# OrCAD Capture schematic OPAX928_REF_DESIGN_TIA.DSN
size A; title: OPA928: 36V, Femotampere Input Bias, High Precision Op Amp; rev: 1.1; note: Datasheet: SBOSA77A - APR '24   EVM: SBOU282A
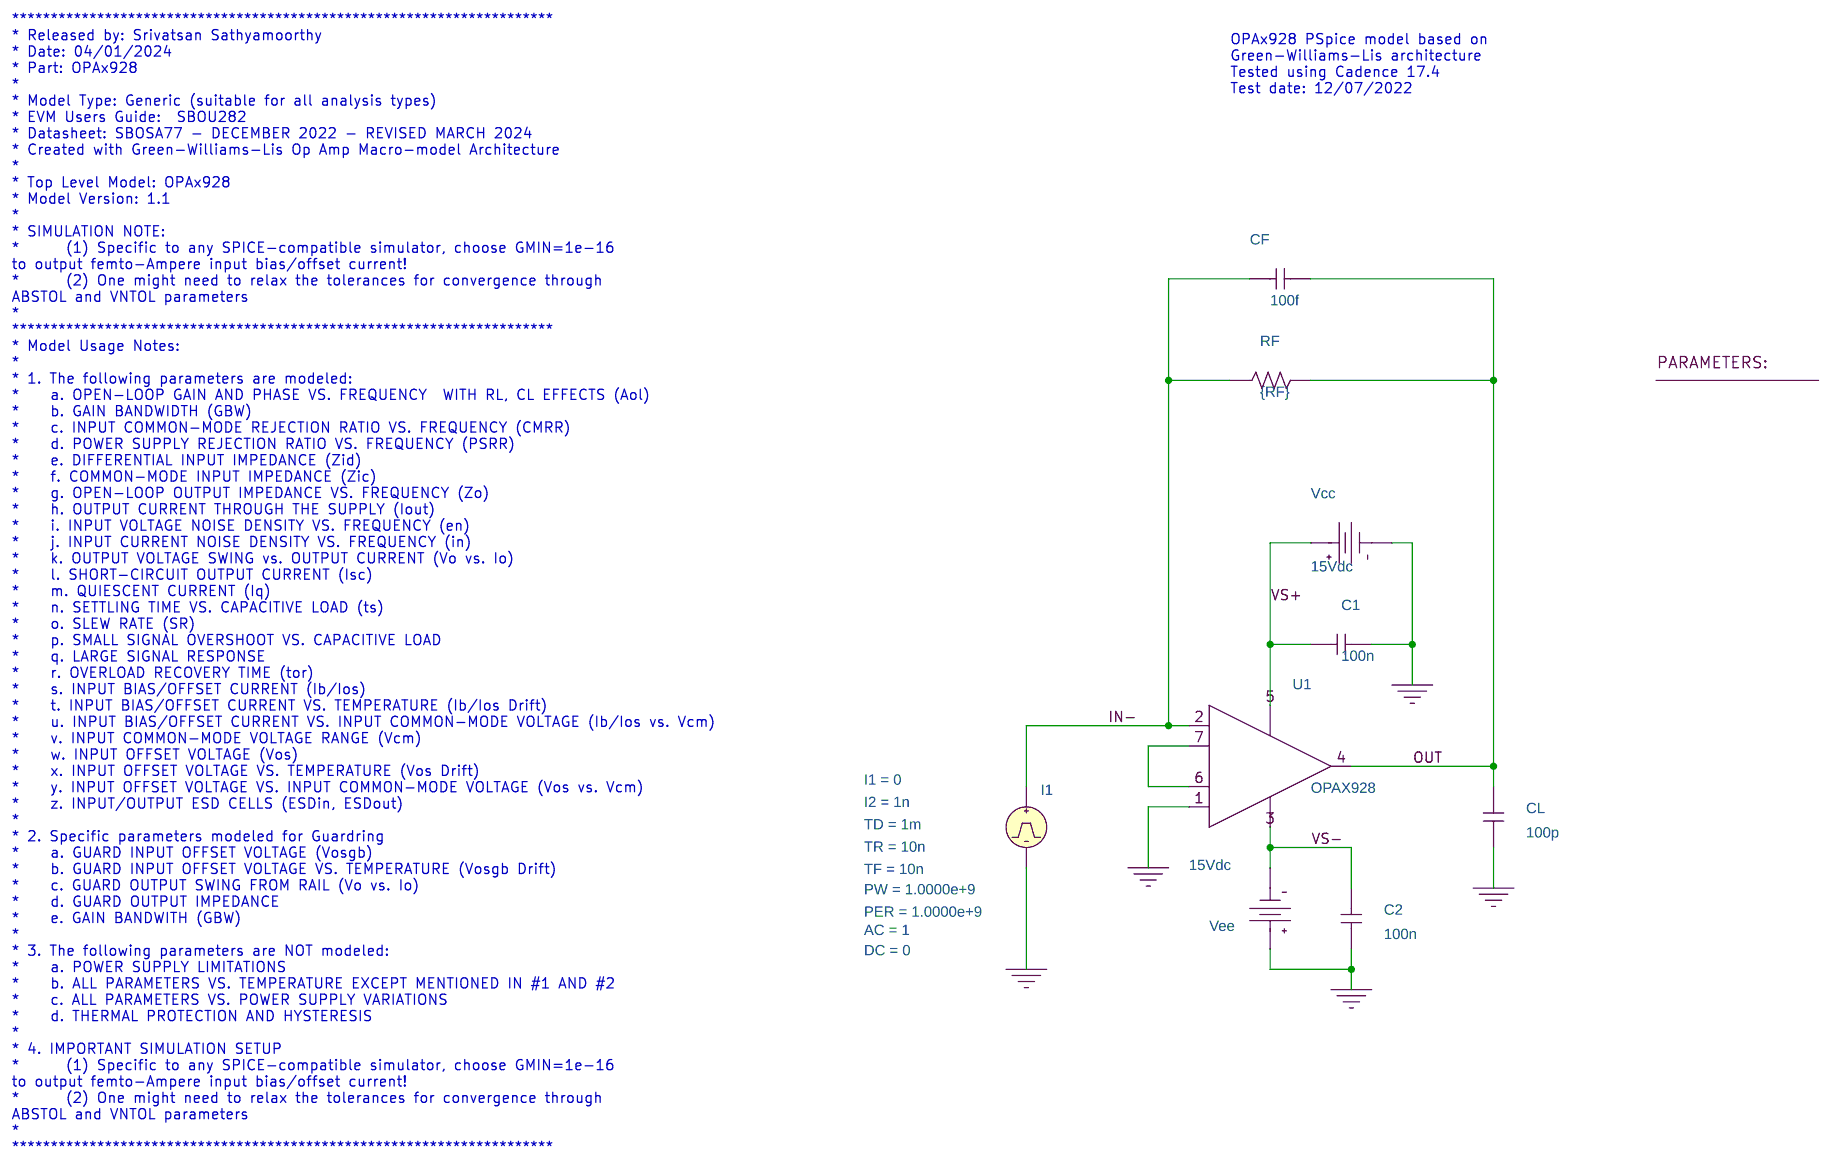
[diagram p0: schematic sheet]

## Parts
1  PARAM
C1  100n  [cap196]
C2  100n  [cap196]
CF  100f  [cap196]
CL  100p  [cap196]
I1  IPULSE
RF  {RF}  [AXRC05]
U1  OPAX928
Vcc  VDC
Vee  VDC

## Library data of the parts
1 = PARAM: RF: 10G
C1 C2 CF CL = C
I1 = IPULSE: AC: 1; AppProp: Pulse$Current$0$-1; DC: 0; I1: 0; I2: 1n; PER: 1.0000e+9; PW: 1.0000e+9; TD: 1m; TF: 10n; TR: 10n
RF = R
U1 = OPAX928
Vcc Vee = VDC: DC: 15Vdc

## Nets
0: C1.2 C2.1 CL.1 I1.2(-) U1.1(+) Vcc.1(-) Vee.0(+)
IN-: CF.2 I1.1(+) RF.1 U1.2(-)
OUT: CF.1 CL.2 RF.2 U1.4(OUT)
VS+: C1.1 U1.5(V+) Vcc.0(+)
VS-: C2.2 U1.3(V-) Vee.1(-)
N00104: U1.6(GRD1) U1.7(GRD2)

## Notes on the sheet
- **********************************************************************
  * Released by: Srivatsan Sathyamoorthy
  * Date: 04/01/2024
  * Part: OPAx928
  *
  * Model Type: Generic (suitable for all analysis types)
  * EVM Users Guide:  SBOU282
  * Datasheet: SBOSA77 - DECEMBER 2022 - REVISED MARCH 2024
  * Created with Green-Williams-Lis Op Amp Macro-model Architecture
  *
  * Top Level Model: OPAx928
  * Model Version: 1.1
  *
  * SIMULATION NOTE:
  *      (1) Specific to any SPICE-compatible simulator, choose GMIN=1e-16
  to output femto-Ampere input bias/offset current!
  *      (2) One might need to relax the tolerances for convergence through
  ABSTOL and VNTOL parameters
  *
  **********************************************************************
  * Model Usage Notes:
  *
  * 1. The following parameters are modeled:
  *    a. OPEN-LOOP GAIN AND PHASE VS. FREQUENCY  WITH RL, CL EFFECTS (Aol)
  *    b. GAIN BANDWIDTH (GBW)
  *    c. INPUT COMMON-MODE REJECTION RATIO VS. FREQUENCY (CMRR)
  *    d. POWER SUPPLY REJECTION RATIO VS. FREQUENCY (PSRR)
  *    e. DIFFERENTIAL INPUT IMPEDANCE (Zid)
  *    f. COMMON-MODE INPUT IMPEDANCE (Zic)
  *    g. OPEN-LOOP OUTPUT IMPEDANCE VS. FREQUENCY (Zo)
  *    h. OUTPUT CURRENT THROUGH THE SUPPLY (Iout)
  *    i. INPUT VOLTAGE NOISE DENSITY VS. FREQUENCY (en)
  *    j. INPUT CURRENT NOISE DENSITY VS. FREQUENCY (in)
  *    k. OUTPUT VOLTAGE SWING vs. OUTPUT CURRENT (Vo vs. Io)
  *    l. SHORT-CIRCUIT OUTPUT CURRENT (Isc)
  *    m. QUIESCENT CURRENT (Iq)
  *    n. SETTLING TIME VS. CAPACITIVE LOAD (ts)
  *    o. SLEW RATE (SR)
  *    p. SMALL SIGNAL OVERSHOOT VS. CAPACITIVE LOAD
  *    q. LARGE SIGNAL RESPONSE
  *    r. OVERLOAD RECOVERY TIME (tor)
  *    s. INPUT BIAS/OFFSET CURRENT (Ib/Ios)
  *    t. INPUT BIAS/OFFSET CURRENT VS. TEMPERATURE (Ib/Ios Drift)
  *    u. INPUT BIAS/OFFSET CURRENT VS. INPUT COMMON-MODE VOLTAGE (Ib/Ios vs. Vcm)
  *    v. INPUT COMMON-MODE VOLTAGE RANGE (Vcm)
  *    w. INPUT OFFSET VOLTAGE (Vos)
  *    x. INPUT OFFSET VOLTAGE VS. TEMPERATURE (Vos Drift)
  *    y. INPUT OFFSET VOLTAGE VS. INPUT COMMON-MODE VOLTAGE (Vos vs. Vcm)
  *    z. INPUT/OUTPUT ESD CELLS (ESDin, ESDout)
  *
  * 2. Specific parameters modeled for Guardring
  *    a. GUARD INPUT OFFSET VOLTAGE (Vosgb)
  *    b. GUARD INPUT OFFSET VOLTAGE VS. TEMPERATURE (Vosgb Drift)
  *    c. GUARD OUTPUT SWING FROM RAIL (Vo vs. Io)
  *    d. GUARD OUTPUT IMPEDANCE
  *    e. GAIN BANDWITH (GBW)
  *
  * 3. The following parameters are NOT modeled:
  *    a. POWER SUPPLY LIMITATIONS
  *    b. ALL PARAMETERS VS. TEMPERATURE EXCEPT MENTIONED IN #1 AND #2
  *    c. ALL PARAMETERS VS. POWER SUPPLY VARIATIONS
  *    d. THERMAL PROTECTION AND HYSTERESIS
  *
  * 4. IMPORTANT SIMULATION SETUP
  *      (1) Specific to any SPICE-compatible simulator, choose GMIN=1e-16
  to output femto-Ampere input bias/offset current!
  *      (2) One might need to relax the tolerances for convergence through
  ABSTOL and VNTOL parameters
  *
  **********************************************************************
- OPAx928 PSpice model based on
  Green-Williams-Lis architecture
  Tested using Cadence 17.4
  Test date: 12/07/2022
